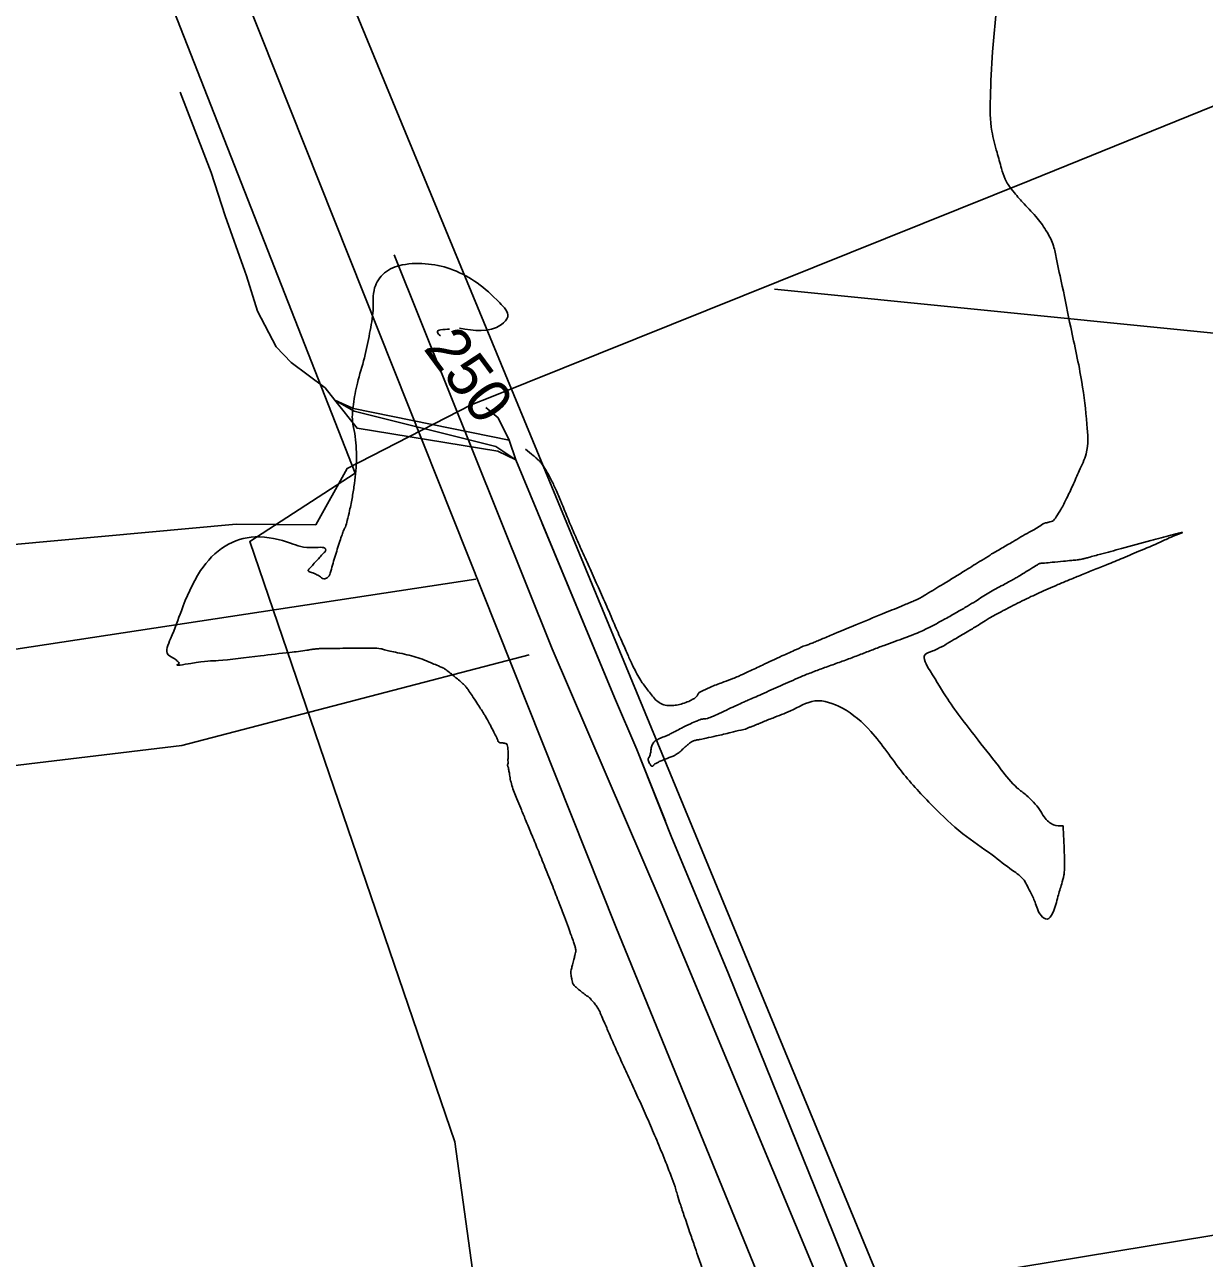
# Model space of a CAD drawing. Extents: x -478464 to -472469, y -1120963 to -1113785.
# Drawn here: x -475970.6 to -475862.9, y -1117239.5 to -1117126.8 of the extents above; entities that cross this region are included whole.
import ezdxf

# ---------------------------------------------------------------- set-up
doc = ezdxf.new("R2010")
doc.units = 0
for name, color, linetype in [('el vedeni_NN', 7, 'Continuous'), ('el vedeni_VVN', 7, 'Continuous'), ('ObPÚ', 7, 'Continuous'), ('plyn_vtl', 7, 'Continuous'), ('silnice', 7, 'Continuous'), ('telekomunikační kabel_O2', 7, 'Continuous'), ('VAK_vodovod', 7, 'Continuous'), ('Vrstevnice_hlavni', 7, 'Continuous'), ('Vrstevnice_popis', 7, 'Continuous')]:
    doc.layers.add(name, color=color, linetype=linetype)

msp = doc.modelspace()

# ---------------------------------------------------------------- linework, layer by layer
at = {"layer": 'el vedeni_NN'}
for points in [[(-475936.884, -1117147.842), (-475922.455, -1117183.822), (-475912.509, -1117206.959)], [(-476142.527, -1117233.564), (-476143.465, -1117231.005), (-476140.291, -1117228.14), (-476109.493, -1117209.467), (-476071.248, -1117205.717), (-476032.928, -1117201.185), (-475993.047, -1117197.048), (-475956.253, -1117192.65), (-475924.554, -1117184.37)], [(-475912.509, -1117206.959), (-475881.908, -1117280.308), (-475845.463, -1117294.572), (-475796.905, -1117294.234), (-475790.107, -1117303.085)]]:
    msp.add_lwpolyline(points, dxfattribs=at)
at = {"layer": 'el vedeni_VVN'}
msp.add_lwpolyline([(-475278.421, -1117142.471), (-475502.649, -1117177.682), (-475743.53, -1117217.796), (-475998.47, -1117259.845), (-476243.025, -1117301.163), (-476469.01, -1117542.153)], dxfattribs=at)
at = {"layer": 'ObPÚ'}
msp.add_lwpolyline([(-475821.3, -1117143.22), (-475827.54, -1117139.09), (-475834.2, -1117137.62), (-475844.36, -1117127.07), (-475878.82, -1117141.03), (-475927.98, -1117160.79), (-475929.84, -1117161.54), (-475941.17, -1117167.34), (-475944.04, -1117172.5), (-475951.31, -1117172.43), (-476004.5, -1117177.28), (-476018.94, -1117179.19), (-476061.7, -1117183.99), (-476084.27, -1117186.17), (-476089.54, -1117186.61), (-476093.95, -1117187.01), (-476104.79, -1117188.01), (-476125.75, -1117189.99)], dxfattribs=at)
at = {"layer": 'plyn_vtl'}
msp.add_lwpolyline([(-475595.138, -1117298.191), (-475598.3, -1117295.92), (-475667.47, -1117237.33), (-475686.33, -1117221.12), (-475738.19, -1117171.6), (-475740.56, -1117170), (-475797.11, -1117162.8), (-475845.33, -1117156.66), (-475902.14, -1117150.95)], dxfattribs=at)
at = {"layer": 'silnice'}
for points in [[(-475903.982, -1117378.322), (-475889.519, -1117318.176), (-475888.389, -1117289.008), (-475895.395, -1117261.196), (-475916.638, -1117209.19), (-475969.886, -1117075.455), (-476021.05, -1116948.737), (-476052.923, -1116863.979), (-476081.44, -1116727.192), (-476114.99, -1116491.378), (-476128.411, -1116405.781), (-476137.637, -1116368.017), (-476162.8, -1116322.7), (-476200.543, -1116268.153), (-476239.965, -1116179.199)], [(-476121.67, -1117200.902), (-476029.858, -1117192.732), (-475929.409, -1117177.447)]]:
    msp.add_lwpolyline(points, dxfattribs=at)
at = {"layer": 'telekomunikační kabel_O2'}
for points in [[(-475967.4, -1117098.97), (-475940.43, -1117167.78), (-475950.06, -1117174), (-475931.33, -1117228.82), (-475924.1, -1117281.32), (-475911.23, -1117358.65), (-475927.92, -1117430.83), (-475926.17, -1117443.9), (-475937.75, -1117500.32), (-475940.1, -1117518.94), (-475929.72, -1117521.06), (-475934.27, -1117556.02), (-475935.89, -1117566.02), (-475936.969, -1117573.032)], [(-475953.59, -1117140.32), (-475956.42, -1117132.98)], [(-475950.5, -1117149.33), (-475952.3, -1117144.28), (-475953.59, -1117140.32)], [(-475942.29, -1117161.11), (-475943.19, -1117159.98), (-475946.28, -1117157.66), (-475947.65, -1117156.22), (-475949.35, -1117152.98), (-475950.35, -1117149.74), (-475950.5, -1117149.33)], [(-475925.77, -1117166.55), (-475927.6, -1117165.32), (-475940.53, -1117162.1), (-475942.29, -1117161.11)], [(-475925.77, -1117166.55), (-475927.41, -1117165.77), (-475940.26, -1117163.67), (-475942.29, -1117161.11)], [(-475941.28, -1117161.55), (-475942.29, -1117161.11)], [(-475926.38, -1117164.74), (-475940.58, -1117161.86), (-475941.28, -1117161.55)], [(-475928.5, -1117161.78), (-475927.37, -1117162.72), (-475926.38, -1117164.74)], [(-475926.38, -1117164.74), (-475925.77, -1117166.55)], [(-475912.112, -1117199.556), (-475914.73, -1117193.01), (-475916.77, -1117188.24), (-475925.77, -1117166.55)], [(-475923.355, -1117172.37), (-475916.77, -1117188.24), (-475914.73, -1117193.01), (-475911.57, -1117200.91), (-475906.35, -1117213.5), (-475897.84, -1117234.5), (-475893.13, -1117246.24), (-475887.26, -1117261.95), (-475881.63, -1117277.42), (-475880.27, -1117280.87), (-475878.41, -1117291.19), (-475878.66, -1117295.04), (-475878.84, -1117303.44), (-475879.2, -1117310.91), (-475879.17, -1117311.76)]]:
    msp.add_lwpolyline(points, dxfattribs=at)
at = {"layer": 'VAK_vodovod'}
msp.add_lwpolyline([(-475961.022, -1117076.006), (-475947.88, -1117107.78), (-475947.26, -1117108.989), (-475886.863, -1117255.251), (-475879.338, -1117287.714), (-475878.218, -1117296.341), (-475877.862, -1117316.562), (-475878.829, -1117320.819), (-475879.236, -1117324.31), (-475879.403, -1117324.54), (-475921.268, -1117487.378), (-475934.347, -1117574.649), (-475937.667, -1117596.666), (-475938.465, -1117600.746), (-475938.582, -1117601.233), (-475938.757, -1117601.897), (-475940.979, -1117601.583)], dxfattribs=at)
at = {"layer": 'Vrstevnice_hlavni'}
for points in [[(-475881.822, -1117138.488), (-475882.298, -1117136.547), (-475882.435, -1117133.482), (-475882.233, -1117129.293), (-475881.692, -1117123.979), (-475881.255, -1117120.961)], [(-475924.869, -1117165.582), (-475924.177, -1117166.164), (-475923.893, -1117166.407), (-475923.671, -1117166.602), (-475923.511, -1117166.749), (-475923.274, -1117167.084), (-475922.96, -1117167.608), (-475922.569, -1117168.319), (-475922.125, -1117169.249), (-475921.627, -1117170.396), (-475921.076, -1117171.761), (-475920.466, -1117173.201), (-475919.798, -1117174.717), (-475919.072, -1117176.307), (-475918.325, -1117177.977), (-475917.556, -1117179.725), (-475916.766, -1117181.553), (-475916.094, -1117183.094), (-475915.54, -1117184.347), (-475915.104, -1117185.312), (-475914.712, -1117186.097), (-475914.365, -1117186.7), (-475914.063, -1117187.123), (-475913.735, -1117187.557), (-475913.38, -1117188.002), (-475913, -1117188.458), (-475912.579, -1117188.775), (-475912.117, -1117188.951), (-475911.613, -1117188.986), (-475911.088, -1117188.941), (-475910.541, -1117188.813), (-475909.972, -1117188.605), (-475909.544, -1117188.384), (-475909.257, -1117188.152), (-475909.111, -1117187.908), (-475908.646, -1117187.607), (-475907.862, -1117187.25), (-475906.759, -1117186.836), (-475905.955, -1117186.527), (-475905.45, -1117186.324), (-475905.244, -1117186.226), (-475904.511, -1117185.883), (-475903.25, -1117185.295), (-475901.462, -1117184.461), (-475900.145, -1117183.861), (-475899.299, -1117183.496), (-475898.924, -1117183.367), (-475898.518, -1117183.211), (-475898.08, -1117183.03), (-475897.611, -1117182.823), (-475896.487, -1117182.352), (-475894.709, -1117181.617), (-475892.277, -1117180.618), (-475890.544, -1117179.904), (-475889.51, -1117179.475), (-475889.176, -1117179.331), (-475888.258, -1117178.808), (-475886.758, -1117177.905), (-475884.675, -1117176.622), (-475883.241, -1117175.734), (-475882.454, -1117175.242), (-475882.317, -1117175.146), (-475882.189, -1117175.064), (-475882.073, -1117174.997), (-475881.967, -1117174.944), (-475881.403, -1117174.622), (-475880.381, -1117174.03), (-475878.901, -1117173.169), (-475877.91, -1117172.594), (-475877.408, -1117172.306), (-475877.395, -1117172.303), (-475877.37, -1117172.3), (-475877.333, -1117172.298), (-475877.284, -1117172.296), (-475877.172, -1117172.269), (-475876.996, -1117172.219), (-475876.756, -1117172.145), (-475876.422, -1117171.763), (-475875.994, -1117171.074), (-475875.471, -1117170.078), (-475874.914, -1117168.901), (-475874.321, -1117167.542), (-475873.694, -1117166.003), (-475873.615, -1117163.305), (-475874.083, -1117159.45), (-475875.099, -1117154.435), (-475875.869, -1117150.689), (-475876.392, -1117148.211), (-475876.669, -1117147.001), (-475877.255, -1117145.76), (-475878.15, -1117144.488), (-475879.354, -1117143.187), (-475880.245, -1117142.157), (-475880.821, -1117141.4), (-475881.084, -1117140.914), (-475881.418, -1117139.944), (-475881.822, -1117138.488)], [(-475930.918, -1117154.529), (-475927.091, -1117154.196), (-475926.503, -1117153.48), (-475927.24, -1117152.214), (-475929.302, -1117150.397), (-475931.471, -1117149.215), (-475933.748, -1117148.667), (-475936.132, -1117148.753), (-475937.769, -1117149.482), (-475938.66, -1117150.856), (-475938.804, -1117152.873), (-475939.115, -1117154.995), (-475939.594, -1117157.22), (-475940.24, -1117159.55), (-475940.601, -1117161.482), (-475940.678, -1117163.016), (-475940.47, -1117164.152), (-475940.352, -1117165.284), (-475940.323, -1117166.413), (-475940.383, -1117167.539), (-475940.507, -1117168.708), (-475940.696, -1117169.92), (-475940.948, -1117171.176), (-475941.162, -1117172.102), (-475941.336, -1117172.697), (-475941.472, -1117172.962), (-475941.64, -1117173.385), (-475941.84, -1117173.966), (-475942.072, -1117174.704), (-475942.295, -1117175.442), (-475942.51, -1117176.178), (-475942.715, -1117176.914), (-475942.981, -1117177.326), (-475943.307, -1117177.413), (-475943.694, -1117177.176), (-475944.026, -1117176.997), (-475944.304, -1117176.874), (-475944.528, -1117176.808), (-475944.67, -1117176.742), (-475944.729, -1117176.675), (-475944.706, -1117176.609), (-475944.521, -1117176.383), (-475944.174, -1117175.997), (-475943.665, -1117175.452), (-475943.322, -1117175.07), (-475943.144, -1117174.851), (-475943.131, -1117174.794), (-475944.198, -1117174.565), (-475946.345, -1117174.163), (-475949.572, -1117173.588), (-475952.308, -1117174.424), (-475954.553, -1117176.67), (-475956.307, -1117180.326), (-475957.293, -1117182.884), (-475957.511, -1117184.344), (-475956.96, -1117184.706), (-475956.631, -1117184.974), (-475956.523, -1117185.148), (-475956.636, -1117185.228), (-475955.435, -1117185.138), (-475952.922, -1117184.878), (-475949.095, -1117184.447), (-475946.401, -1117184.135), (-475944.839, -1117183.942), (-475944.409, -1117183.867), (-475944.026, -1117183.817), (-475943.69, -1117183.791), (-475943.401, -1117183.789), (-475942.688, -1117183.78), (-475941.551, -1117183.761), (-475939.989, -1117183.735), (-475938.839, -1117183.747), (-475938.1, -1117183.797), (-475937.772, -1117183.886), (-475937.265, -1117184.007), (-475936.577, -1117184.16), (-475935.71, -1117184.344), (-475934.887, -1117184.569), (-475934.109, -1117184.835), (-475933.375, -1117185.14), (-475932.838, -1117185.366), (-475932.498, -1117185.513), (-475932.355, -1117185.581), (-475932.074, -1117185.779), (-475931.655, -1117186.106), (-475931.097, -1117186.562), (-475930.689, -1117186.908), (-475930.429, -1117187.143), (-475930.318, -1117187.267), (-475930.097, -1117187.576), (-475929.766, -1117188.071), (-475929.325, -1117188.751), (-475928.979, -1117189.287), (-475928.728, -1117189.677), (-475928.572, -1117189.922), (-475928.361, -1117190.294), (-475928.094, -1117190.794)], [(-475932.653, -1117155.22), (-475932.923, -1117154.883), (-475932.876, -1117154.759), (-475932.647, -1117154.679), (-475931.823, -1117154.607)], [(-475900.706, -1117186.785), (-475899.805, -1117186.392), (-475898.808, -1117185.988), (-475897.717, -1117185.575), (-475896.532, -1117185.153), (-475895.378, -1117184.731), (-475894.256, -1117184.308), (-475893.166, -1117183.885), (-475892.136, -1117183.495), (-475891.165, -1117183.136), (-475890.254, -1117182.81), (-475889.46, -1117182.504), (-475888.782, -1117182.22), (-475888.221, -1117181.958), (-475887.479, -1117181.575), (-475886.556, -1117181.073), (-475885.451, -1117180.451), (-475884.521, -1117179.91), (-475883.768, -1117179.45), (-475883.19, -1117179.071), (-475882.583, -1117178.7), (-475881.946, -1117178.336), (-475881.28, -1117177.98), (-475880.766, -1117177.703), (-475880.403, -1117177.507), (-475880.193, -1117177.39), (-475879.832, -1117177.175), (-475879.321, -1117176.862), (-475878.659, -1117176.449), (-475878.199, -1117176.17), (-475877.94, -1117176.025), (-475877.882, -1117176.013), (-475877.499, -1117175.973), (-475876.792, -1117175.905), (-475875.76, -1117175.809), (-475875.003, -1117175.737), (-475874.521, -1117175.688), (-475874.314, -1117175.663), (-475874.071, -1117175.617), (-475873.793, -1117175.551), (-475873.478, -1117175.465), (-475872.371, -1117175.165), (-475870.469, -1117174.652), (-475867.775, -1117173.924), (-475865.95, -1117173.435), (-475864.996, -1117173.184), (-475864.912, -1117173.172), (-475865.491, -1117173.438), (-475866.735, -1117173.982), (-475868.643, -1117174.805), (-475870.335, -1117175.522), (-475871.814, -1117176.133), (-475873.078, -1117176.639), (-475874.242, -1117177.11), (-475875.308, -1117177.545), (-475876.274, -1117177.946), (-475877.165, -1117178.329), (-475877.982, -1117178.695), (-475878.725, -1117179.044), (-475879.521, -1117179.431), (-475880.372, -1117179.858), (-475881.277, -1117180.323), (-475881.999, -1117180.711), (-475882.54, -1117181.02), (-475882.898, -1117181.252), (-475883.522, -1117181.635), (-475884.411, -1117182.169), (-475885.565, -1117182.855), (-475886.364, -1117183.326), (-475886.808, -1117183.582), (-475886.896, -1117183.624), (-475887.19, -1117183.764), (-475887.691, -1117184.002), (-475888.399, -1117184.338), (-475887.946, -1117185.807), (-475886.332, -1117188.408), (-475883.558, -1117192.141), (-475881.439, -1117194.845), (-475879.975, -1117196.521), (-475879.166, -1117197.167), (-475878.487, -1117197.821), (-475877.938, -1117198.482), (-475877.52, -1117199.151), (-475877.096, -1117199.613), (-475876.667, -1117199.869), (-475875.8, -1117199.969)], [(-475875.8, -1117199.969), (-475875.68, -1117202.403), (-475875.658, -1117203.359), (-475875.673, -1117204.054), (-475875.726, -1117204.488), (-475875.922, -1117205.276), (-475876.259, -1117206.418), (-475876.739, -1117207.915), (-475877.248, -1117208.499), (-475877.786, -1117208.171), (-475878.353, -1117206.931), (-475878.805, -1117205.979), (-475879.141, -1117205.316), (-475879.361, -1117204.941), (-475880.402, -1117204.046), (-475882.264, -1117202.632), (-475884.948, -1117200.698), (-475887.689, -1117198.176), (-475890.488, -1117195.066), (-475893.345, -1117191.367), (-475895.998, -1117189.203), (-475898.449, -1117188.572), (-475900.697, -1117189.475), (-475902.312, -1117190.127), (-475903.293, -1117190.526), (-475903.642, -1117190.674), (-475903.924, -1117190.79), (-475904.137, -1117190.873), (-475904.284, -1117190.925), (-475904.422, -1117190.977), (-475904.554, -1117191.031), (-475904.678, -1117191.085), (-475905.203, -1117191.224), (-475906.13, -1117191.449), (-475907.459, -1117191.76), (-475908.393, -1117191.972), (-475908.932, -1117192.087), (-475909.077, -1117192.105), (-475909.225, -1117192.131), (-475909.377, -1117192.167), (-475909.532, -1117192.212), (-475909.671, -1117192.27), (-475909.793, -1117192.34), (-475909.9, -1117192.424), (-475910.088, -1117192.585), (-475910.358, -1117192.824), (-475910.71, -1117193.139), (-475911.018, -1117193.381), (-475911.281, -1117193.547), (-475911.499, -1117193.639), (-475911.684, -1117193.715), (-475911.836, -1117193.776), (-475911.953, -1117193.823), (-475912.145, -1117193.899), (-475912.41, -1117194.007), (-475912.749, -1117194.146), (-475912.996, -1117194.272), (-475913.15, -1117194.387), (-475913.212, -1117194.49), (-475913.28, -1117194.535), (-475913.355, -1117194.521), (-475913.436, -1117194.45), (-475913.514, -1117194.346), (-475913.588, -1117194.21), (-475913.659, -1117194.043), (-475913.681, -1117193.9), (-475913.654, -1117193.781), (-475913.58, -1117193.687), (-475913.508, -1117193.483), (-475913.439, -1117193.17), (-475913.374, -1117192.747), (-475913.218, -1117192.413), (-475912.972, -1117192.166), (-475912.636, -1117192.007), (-475912.366, -1117191.886), (-475912.161, -1117191.802), (-475912.023, -1117191.756), (-475911.881, -1117191.697), (-475911.735, -1117191.623), (-475911.586, -1117191.536), (-475911.219, -1117191.345), (-475910.634, -1117191.049), (-475909.83, -1117190.648), (-475909.191, -1117190.371), (-475908.716, -1117190.217), (-475908.406, -1117190.187), (-475907.901, -1117190.024), (-475907.201, -1117189.727), (-475906.307, -1117189.297), (-475905.57, -1117188.951), (-475904.991, -1117188.688), (-475904.57, -1117188.508), (-475904.007, -1117188.261), (-475903.302, -1117187.946), (-475902.455, -1117187.563), (-475901.59, -1117187.176), (-475900.706, -1117186.785)], [(-475928.094, -1117190.794), (-475927.771, -1117191.421), (-475927.547, -1117191.876), (-475927.42, -1117192.158), (-475927.392, -1117192.268), (-475927.318, -1117192.345), (-475927.2, -1117192.388), (-475927.036, -1117192.399), (-475926.883, -1117192.418), (-475926.743, -1117192.446), (-475926.615, -1117192.482), (-475926.527, -1117192.705), (-475926.478, -1117193.114), (-475926.469, -1117193.711), (-475926.473, -1117194.117), (-475926.491, -1117194.334), (-475926.521, -1117194.361), (-475926.53, -1117194.407), (-475926.518, -1117194.472), (-475926.483, -1117194.555), (-475926.431, -1117194.79), (-475926.36, -1117195.176), (-475926.272, -1117195.712), (-475926.126, -1117196.282), (-475925.925, -1117196.884), (-475925.666, -1117197.52), (-475925.318, -1117198.365), (-475924.88, -1117199.422), (-475924.352, -1117200.688), (-475923.763, -1117202.127), (-475923.112, -1117203.739), (-475922.399, -1117205.524), (-475921.805, -1117207.037), (-475921.328, -1117208.278), (-475920.97, -1117209.247), (-475920.693, -1117210.011), (-475920.496, -1117210.569), (-475920.379, -1117210.921), (-475920.31, -1117211.202), (-475920.289, -1117211.41), (-475920.315, -1117211.546), (-475920.374, -1117211.801), (-475920.467, -1117212.174), (-475920.594, -1117212.666), (-475920.682, -1117213.023), (-475920.733, -1117213.246), (-475920.746, -1117213.334), (-475920.736, -1117213.492), (-475920.704, -1117213.718), (-475920.649, -1117214.013), (-475920.599, -1117214.235), (-475920.552, -1117214.384), (-475920.51, -1117214.46), (-475920.366, -1117214.609), (-475920.122, -1117214.83), (-475919.777, -1117215.123), (-475919.503, -1117215.343), (-475919.3, -1117215.489), (-475919.169, -1117215.562), (-475918.99, -1117215.724), (-475918.765, -1117215.973), (-475918.494, -1117216.31), (-475918.275, -1117216.627), (-475918.11, -1117216.924), (-475917.998, -1117217.199), (-475917.707, -1117217.875), (-475917.239, -1117218.951), (-475916.592, -1117220.428), (-475915.908, -1117221.958), (-475915.187, -1117223.541), (-475914.428, -1117225.177), (-475913.666, -1117226.891), (-475912.901, -1117228.682), (-475912.132, -1117230.55), (-475911.572, -1117231.97), (-475911.22, -1117232.944), (-475911.078, -1117233.47), (-475910.81, -1117234.327), (-475910.417, -1117235.517), (-475909.897, -1117237.038), (-475909.473, -1117238.279), (-475909.144, -1117239.239), (-475908.911, -1117239.919), (-475908.686, -1117240.672), (-475908.471, -1117241.496), (-475908.263, -1117242.393), (-475907.931, -1117243.542), (-475907.474, -1117244.942), (-475906.892, -1117246.594), (-475906.238, -1117248.44), (-475905.515, -1117250.481), (-475904.72, -1117252.716), (-475904.051, -1117254.726), (-475903.508, -1117256.51), (-475903.092, -1117258.07), (-475902.721, -1117260.055), (-475902.398, -1117262.467)]]:
    msp.add_spline(points, degree=3, dxfattribs=at)

# ---------------------------------------------------------------- texts
at = {"layer": 'Vrstevnice_popis'}
msp.add_text(' 250 ', height=4, rotation=306.44995, dxfattribs=at).set_placement((-475935.162, -1117155.18))

doc.saveas('drawing.dxf')
